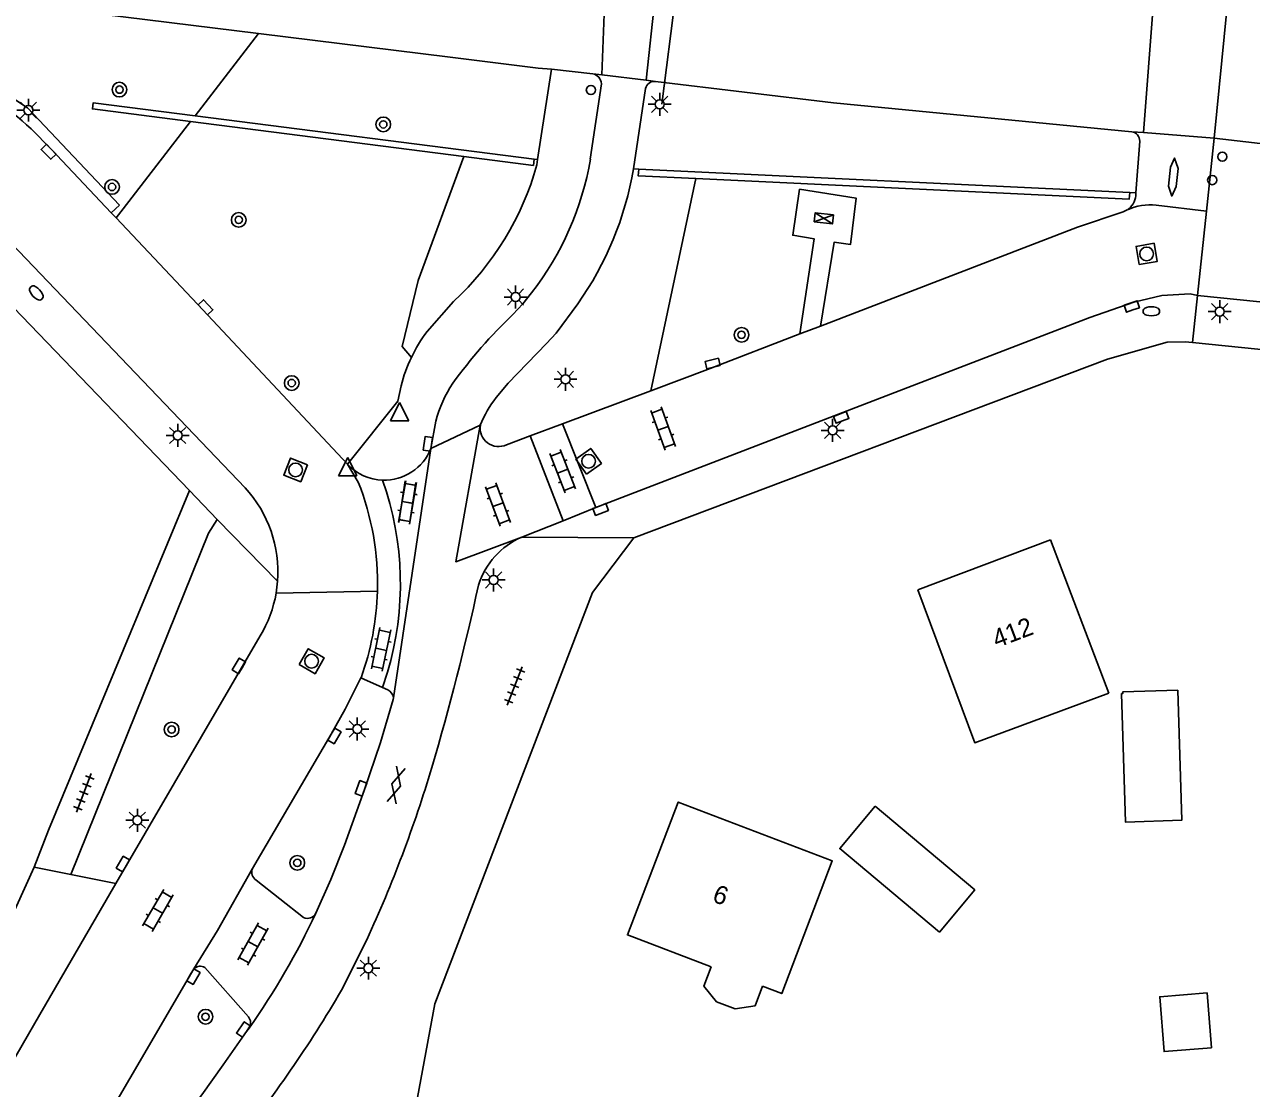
# Model space of a CAD drawing. Extents: x 132994 to 136000, y 393499 to 395512.
# Drawn here: x 133850.3 to 133917.2, y 394939.5 to 394997.5 of the extents above; entities that cross this region are included whole.
import ezdxf

# ---------------------------------------------------------------- set-up
doc = ezdxf.new("R2010")
doc.units = 0
for name, color, linetype in [('gg-anno-huisnummerreeks BGT', 7, 'Continuous'), ('gg-bbg-bijgebouw', 7, 'Continuous'), ('gg-bbg-gedigitaliseerde bebouwing', 7, 'Continuous'), ('gg-bbg-gedigitaliseerde bijgebouw', 7, 'Continuous'), ('gg-bbg-hoofdgebouw', 7, 'Continuous'), ('gg-knt-verharding', 7, 'Continuous'), ('gg-knt-verharding nz', 7, 'Continuous'), ('gt-grn-groengrens', 7, 'Continuous'), ('gt-grn-weggrens', 7, 'Continuous'), ('gt-knt-lijn portaal', 7, 'Continuous'), ('gt-symb-boom', 7, 'Continuous'), ('gt-symb-brandkraan', 7, 'Continuous'), ('gt-symb-drukknoppaal', 7, 'Continuous'), ('gt-symb-gesloten verharding', 7, 'Continuous'), ('gt-symb-klinker verharding', 7, 'Continuous'), ('gt-symb-kolk', 7, 'Continuous'), ('gt-symb-lichtmast', 7, 'Continuous'), ('gt-symb-rioolschacht', 7, 'Continuous'), ('gt-symb-tegel verharding', 7, 'Continuous'), ('gt-symb-verkeersregelinstallatiekast', 7, 'Continuous'), ('gt-symb-verkeersregelinstallatiepaal', 7, 'Continuous'), ('gt-symb-waterafsluiter', 7, 'Continuous')]:
    doc.layers.add(name, color=color, linetype=linetype)

# ---------------------------------------------------------------- blocks, each defined once
blk = doc.blocks.new('gt0-VIPAAL')
at = {"layer": 'gt-symb-verkeersregelinstallatiepaal'}
blk.add_circle((0, 0), 0.25, dxfattribs=at)
blk = doc.blocks.new('gt0-DPAAL')
at = {"layer": 'gt-symb-drukknoppaal'}
blk.add_circle((0, 0), 0.25, dxfattribs=at)
blk = doc.blocks.new('gt0-KOLK')
at = {"layer": 'gt-symb-kolk'}
blk.add_lwpolyline([(0, 0), (0.375, 0), (0.375, 0.4), (-0.375, 0.4), (-0.375, 0), (0, 0)], dxfattribs=at)
blk = doc.blocks.new('gt0-RS')
at = {"layer": 'gt-symb-rioolschacht'}
blk.add_lwpolyline([(-0.5, -0.5), (0.5, -0.5), (0.5, 0.5), (-0.5, 0.5)], close=True, dxfattribs=at)
blk.add_circle((0, 0), 0.375, dxfattribs=at)
blk = doc.blocks.new('gt0-BR')
at = {"layer": 'gt-symb-brandkraan'}
for centre, radius, start, end in [((-0.244, 0), 0.206, 107.56694, 252.43307), ((0.599, -2.664), 3, 106.89205, 107.56694), ((0, -0.691), 0.938, 73.10799, 106.89205), ((-0.599, -2.664), 3, 72.43309, 73.10799), ((0.244, 0), 0.206, 287.56695, 72.43309), ((0.599, 2.664), 3, 252.43307, 253.10797), ((0, 0.691), 0.938, 253.10797, 286.89206), ((-0.599, 2.664), 3, 286.89206, 287.56695)]:
    blk.add_arc(centre, radius, start, end, dxfattribs=at)
blk = doc.blocks.new('gt0-BOOM')
at = {"layer": 'gt-symb-boom'}
for radius in [0.4, 0.2]:
    blk.add_circle((0, 0), radius, dxfattribs=at)
blk = doc.blocks.new('gt0-LMAST')
at = {"layer": 'gt-symb-lichtmast'}
for p, q in [((-0.182, 0.173), (-0.447, 0.438)), ((-0.005, 0.246), (-0.005, 0.621)), ((0.172, 0.173), (0.437, 0.438)), ((-0.255, -0.004), (-0.63, -0.004)), ((-0.182, -0.181), (-0.447, -0.446)), ((-0.005, -0.254), (-0.005, -0.629)), ((0.437, -0.446), (0.172, -0.181)), ((0.245, -0.004), (0.62, -0.004))]:
    blk.add_line(p, q, dxfattribs=at)
blk.add_circle((-0.005, -0.004), 0.25, dxfattribs=at)
blk = doc.blocks.new('gt0-VRIKST')
at = {"layer": 'gt-symb-verkeersregelinstallatiekast'}
for p, q in [((-0.501, -0.249), (0.501, 0.249)), ((-0.501, 0.249), (0.501, -0.249))]:
    blk.add_line(p, q, dxfattribs=at)
blk.add_lwpolyline([(0.501, 0.249), (-0.501, 0.249), (-0.501, -0.249), (0.501, -0.249)], close=True, dxfattribs=at)
blk = doc.blocks.new('gt0-KL1')
at = {"layer": 'gt-symb-klinker verharding'}
for p, q in [((-1.15, 0.3), (1.15, 0.3)), ((-1, -0.3), (-1, 0.3)), ((-0.5, 0.3), (-0.5, 0.45)), ((0, -0.3), (0, 0.3)), ((0.5, 0.3), (0.5, 0.45)), ((1, -0.3), (1, 0.3)), ((-1.15, -0.3), (1.15, -0.3)), ((-0.5, -0.45), (-0.5, -0.3)), ((0.5, -0.45), (0.5, -0.3))]:
    blk.add_line(p, q, dxfattribs=at)
blk = doc.blocks.new('gt0-WAFSL')
at = {"layer": 'gt-symb-waterafsluiter'}
for p, q in [((-0.5, -0.333), (0, 0.667)), ((0, 0.667), (0.5, -0.333)), ((0.5, -0.333), (-0.5, -0.333))]:
    blk.add_line(p, q, dxfattribs=at)
blk = doc.blocks.new('gt0-TEG1')
at = {"layer": 'gt-symb-tegel verharding'}
for p, q in [((-1.125, 0), (1.125, 0)), ((-0.9, -0.25), (-0.9, 0.25)), ((-0.45, -0.25), (-0.45, 0.25)), ((0, -0.25), (0, 0.25)), ((0.45, -0.25), (0.45, 0.25)), ((0.9, -0.25), (0.9, 0.25))]:
    blk.add_line(p, q, dxfattribs=at)
blk = doc.blocks.new('gt0-GESVH1')
at = {"layer": 'gt-symb-gesloten verharding'}
for p, q in [((-0.992, -0.261), (0.008, 0.239)), ((0.008, -0.261), (-0.992, 0.239)), ((0.008, 0.239), (1.008, -0.261)), ((1.008, 0.239), (0.008, -0.261))]:
    blk.add_line(p, q, dxfattribs=at)

msp = doc.modelspace()

# ---------------------------------------------------------------- linework, layer by layer
at = {"layer": 'gg-bbg-bijgebouw'}
for points in [[(133910.122, 394960.997), (133910.197, 394961), (133910.194, 394961.08), (133913.191, 394961.174), (133913.414, 394954.078), (133910.336, 394953.981), (133910.122, 394960.997)], [(133896.675, 394954.842), (133894.743, 394952.535), (133900.186, 394947.976), (133902.118, 394950.283), (133896.675, 394954.842)]]:
    msp.add_lwpolyline(points, dxfattribs=at)
at = {"layer": 'gg-bbg-gedigitaliseerde bebouwing'}
for points in [[(133899, 394966.65), (133902.114, 394958.31), (133909.431, 394961.02)], [(133888.022, 394944.169), (133889.034, 394943.785), (133890.127, 394943.962), (133890.531, 394945.029)]]:
    msp.add_lwpolyline(points, dxfattribs=at)
at = {"layer": 'gg-bbg-gedigitaliseerde bijgebouw'}
msp.add_lwpolyline([(133915.04, 394941.667), (133914.799, 394944.658), (133912.208, 394944.449), (133912.448, 394941.459), (133915.04, 394941.667)], dxfattribs=at)
at = {"layer": 'gg-bbg-hoofdgebouw'}
for p, q in [((133899, 394966.65), (133906.24, 394969.38)), ((133906.24, 394969.38), (133909.431, 394961.02))]:
    msp.add_line(p, q, dxfattribs=at)
for points in [[(133890.531, 394945.029), (133891.58, 394944.63), (133894.34, 394951.87), (133885.93, 394955.07), (133883.16, 394947.83), (133887.727, 394946.094)], [(133887.727, 394946.094), (133887.322, 394945.027), (133888.022, 394944.169)]]:
    msp.add_lwpolyline(points, dxfattribs=at)
at = {"layer": 'gg-knt-verharding'}
for p, q in [((133873.479, 394995.704), (133863.026, 394996.992)), ((133879.016, 394995.05), (133878.256, 394990.126)), ((133881.265, 394994.795), (133879.016, 394995.05)), ((133881.132, 394990.14), (133881.733, 394994.255)), ((133884.151, 394993.998), (133883.483, 394989.615)), ((133910.686, 394991.635), (133911.333, 394991.593)), ((133911.333, 394991.593), (133915.182, 394991.281)), ((133910.912, 394988.302), (133911.118, 394991.117)), ((133915.182, 394991.281), (133914.759, 394987.306)), ((133918.173, 394990.943), (133915.182, 394991.281)), ((133878.256, 394990.126), (133878.21, 394989.826)), ((133862.288, 394972.217), (133846.386, 394988.819)), ((133859.247, 394972.063), (133843.346, 394988.59)), ((133910.901, 394988.15), (133910.912, 394988.302)), ((133912.018, 394987.641), (133914.759, 394987.306)), ((133854.985, 394987.216), (133855.244, 394986.942)), ((133910.442, 394987.376), (133910.223, 394987.265)), ((133914.759, 394987.306), (133914.27, 394982.706)), ((133873.672, 394982.381), (133872.22, 394980.739)), ((133908.4, 394981.51), (133881.431, 394971.142)), ((133892.571, 394980.611), (133893.687, 394981.04)), ((133887.68, 394978.73), (133892.571, 394980.611)), ((133884.428, 394977.512), (133887.68, 394978.73)), ((133870.807, 394977.776), (133870.626, 394976.95)), ((133879.614, 394975.708), (133884.428, 394977.512)), ((133867.886, 394973.502), (133870.626, 394976.95)), ((133872.427, 394974.363), (133872.702, 394975.851)), ((133877.85, 394975.048), (133879.614, 394975.708)), ((133881.431, 394971.142), (133879.614, 394975.708)), ((133876.553, 394974.562), (133877.85, 394975.048)), ((133877.85, 394975.048), (133879.652, 394970.417)), ((133870.381, 394960.765), (133872.427, 394974.363)), ((133868.464, 394972.526), (133867.886, 394973.502)), ((133851.551, 394953.543), (133859.247, 394972.063)), ((133879.652, 394970.417), (133881.431, 394971.142)), ((133860.761, 394970.479), (133860.284, 394969.736)), ((133864.063, 394967.123), (133860.761, 394970.479)), ((133879.652, 394970.417), (133877.387, 394969.525)), ((133852.769, 394951.12), (133860.284, 394969.736)), ((133863.982, 394966.47), (133864.063, 394967.123)), ((133855.239, 394950.627), (133863.113, 394964.14)), ((133870.057, 394962.157), (133869.782, 394961.321)), ((133868.615, 394961.851), (133867.754, 394960.139)), ((133869.782, 394961.321), (133868.615, 394961.851)), ((133870.073, 394961.189), (133869.782, 394961.321)), ((133850.771, 394951.519), (133851.551, 394953.543)), ((133855.239, 394950.627), (133851.089, 394943.477)), ((133852.769, 394951.12), (133855.239, 394950.627)), ((133862.898, 394950.816), (133865.481, 394948.778)), ((133868.937, 394947.565), (133867.551, 394944.812)), ((133862.467, 394943.354), (133860.091, 394946.056)), ((133851.089, 394943.477), (133849.149, 394940.135))]:
    msp.add_line(p, q, dxfattribs=at)
for points in [[(133863.026, 394996.992), (133848.377, 394998.796), (133838.166, 395000)], [(133873.479, 394995.704), (133878.293, 394995.107), (133879.016, 394995.05)], [(133910.686, 394991.635), (133894.413, 394993.207), (133884.689, 394994.385)], [(133850.609, 394991.794), (133851.705, 394990.685), (133854.985, 394987.216)], [(133912.695, 394988.663), (133912.868, 394988.127), (133913.108, 394988.649), (133913.219, 394989.631), (133913.023, 394990.197), (133912.789, 394989.699), (133912.695, 394988.663)], [(133893.687, 394981.04), (133894.436, 394985.612), (133895.328, 394985.481), (133895.641, 394988.018), (133892.55, 394988.5), (133892.181, 394985.991), (133893.343, 394985.804), (133892.571, 394980.611)], [(133855.244, 394986.942), (133859.986, 394981.927), (133867.886, 394973.502)], [(133893.687, 394981.04), (133907.73, 394986.44), (133910.223, 394987.265)], [(133876.904, 394981.678), (133877.446, 394982.244), (133877.927, 394982.857)], [(133914.27, 394982.706), (133913.87, 394982.8), (133912.33, 394982.7), (133910.79, 394982.35), (133908.4, 394981.51)], [(133880.446, 394982.245), (133879.266, 394980.647), (133878.748, 394980.093), (133876.644, 394977.926), (133875.995, 394977.142)], [(133913.996, 394980.139), (133913.59, 394980.18), (133912.61, 394980.16), (133909.36, 394979.23), (133883.51, 394969.49)], [(133942.56, 394977.82), (133942.56, 394977.66), (133938.56, 394978.04), (133938.51, 394977.92), (133924.9, 394979.28), (133924.87, 394979.04), (133913.996, 394980.139)], [(133875.128, 394975.629), (133873.786, 394968.181), (133877.387, 394969.525)], [(133871.116, 394935.811), (133872.649, 394944.058), (133881.252, 394966.506), (133883.51, 394969.49)], [(133866.152, 394949.008), (133866.965, 394950.851), (133867.713, 394952.715), (133868.808, 394955.756), (133869.674, 394958.314), (133870.376, 394960.662), (133870.381, 394960.765)], [(133867.754, 394960.139), (133866.994, 394958.779), (133862.697, 394951.443)], [(133850.771, 394951.519), (133849.288, 394948.238), (133845.885, 394942.434)], [(133859.495, 394945.981), (133860.778, 394948.072), (133862.697, 394951.443)], [(133851.898, 394932.933), (133852.499, 394934.006), (133859.495, 394945.981)], [(133854.954, 394932.825), (133856.802, 394935.184), (133858.69, 394937.504), (133859.926, 394939.095), (133861.097, 394940.731), (133862.358, 394942.553), (133862.505, 394942.738)]]:
    msp.add_lwpolyline(points, dxfattribs=at)
for centre, radius, start, end in [((133842.053, 394982.69), 12.494, 46.77674, 70.9578), ((133881.168, 394994.238), 0.566, 1.74583, 80.08294), ((133884.637, 394993.89), 0.498, 84.03151, 167.42575), ((133910.624, 394991.145), 0.494, 356.81029, 82.84436), ((133865.151, 394992.826), 16.206, 322.03586, 350.45882), ((133862.802, 394994.112), 15.993, 312.8173, 344.45503), ((133865.828, 394992.579), 17.902, 324.74061, 350.46863), ((133909.866, 394988.241), 1.039, 303.67342, 354.98873), ((133911.72, 394984.596), 3.059, 84.4031, 114.68658), ((133896.917, 394960.915), 28.838, 133.94682, 143.87147), ((133878.83, 394975.774), 8.267, 143.0909, 154.54072), ((133878.815, 394975.768), 8.256, 154.45813, 165.92581), ((133879.298, 394974.145), 6.813, 146.37387, 165.5007), ((133880.847, 394973.357), 6.154, 142.04055, 158.33113), ((133876.126, 394975.476), 1.009, 171.3007, 295.04962), ((133869.885, 394975.359), 2.73, 268.15784, 338.60676), ((133869.888, 394975.359), 2.73, 222.84913, 268.09591), ((133857.316, 394967.628), 6.766, 355.71613, 42.70556), ((133854.423, 394966.988), 15.094, 358.44616, 21.52362), ((133853.924, 394966.996), 16.843, 343.30334, 19.54089), ((133879.093, 394965.608), 4.272, 113.5374, 162.25859), ((133738.544, 394996.467), 139.644, 343.56768, 347.78044), ((133857.319, 394967.628), 6.763, 328.95167, 350.14119), ((133854.419, 394966.99), 15.098, 340.09905, 358.43929), ((133869.891, 394960.733), 0.491, 3.72684, 68.2636), ((133803.273, 394977.714), 72.254, 335.33813, 343.3108), ((133863.13, 394951.236), 0.48, 154.49329, 241.05573), ((133827.299, 394967.412), 42.992, 324.97601, 334.6544), ((133865.701, 394949.229), 0.502, 243.92413, 333.91643), ((133859.846, 394945.596), 0.521, 61.97854, 132.36614), ((133809.023, 394978.984), 67.774, 320.95606, 329.7215), ((133862.066, 394943.02), 0.522, 327.26355, 39.79647)]:
    msp.add_arc(centre, radius, start, end, dxfattribs=at)
at = {"layer": 'gg-knt-verharding nz'}
for p, q in [((133882.166, 395005.026), (133881.759, 394994.736)), ((133885.276, 395004.635), (133884.171, 394994.447)), ((133911.863, 394998.7), (133911.333, 394991.593)), ((133915.881, 394998.286), (133915.182, 394991.281)), ((133881.265, 394994.795), (133881.759, 394994.736)), ((133881.759, 394994.736), (133884.171, 394994.447)), ((133884.171, 394994.447), (133884.689, 394994.385)), ((133914.27, 394982.706), (133934.487, 394980.66)), ((133850.771, 394951.519), (133852.769, 394951.12))]:
    msp.add_line(p, q, dxfattribs=at)
at = {"layer": 'gt-grn-groengrens'}
for p, q in [((133863.026, 394996.992), (133859.56, 394992.514)), ((133859.313, 394992.195), (133855.629, 394987.436)), ((133859.313, 394992.195), (133874.233, 394990.289)), ((133878.073, 394990.149), (133859.56, 394992.514)), ((133874.233, 394990.289), (133878.028, 394989.804)), ((133878.028, 394989.804), (133878.073, 394990.149)), ((133878.073, 394990.149), (133878.256, 394990.126)), ((133883.774, 394989.605), (133883.483, 394989.615)), ((133910.58, 394988.318), (133883.774, 394989.605)), ((133886.889, 394989.088), (133884.428, 394977.512)), ((133910.58, 394988.318), (133910.912, 394988.302)), ((133854.985, 394987.216), (133855.435, 394987.641)), ((133855.244, 394986.942), (133855.629, 394987.436))]:
    msp.add_line(p, q, dxfattribs=at)
for points in [[(133846.453, 394995.188), (133848.227, 394994.385), (133850.419, 394992.944), (133855.435, 394987.641)], [(133859.56, 394992.514), (133854.003, 394993.224), (133853.958, 394992.879), (133859.313, 394992.195)], [(133874.233, 394990.289), (133871.738, 394983.522), (133870.862, 394979.922), (133871.366, 394979.328)], [(133883.774, 394989.605), (133883.736, 394989.239), (133886.889, 394989.088)], [(133886.889, 394989.088), (133910.542, 394987.952), (133910.58, 394988.318)]]:
    msp.add_lwpolyline(points, dxfattribs=at)
at = {"layer": 'gt-grn-weggrens'}
for p, q in [((133914.27, 394982.706), (133913.996, 394980.139)), ((133872.427, 394974.363), (133875.128, 394975.629)), ((133860.761, 394970.479), (133859.247, 394972.063)), ((133883.51, 394969.49), (133877.387, 394969.525)), ((133869.511, 394966.579), (133863.982, 394966.47))]:
    msp.add_line(p, q, dxfattribs=at)
at = {"layer": 'gt-knt-lijn portaal'}
msp.add_line((133885.041, 394993.151), (133886.188, 395002.329), dxfattribs=at)

# ---------------------------------------------------------------- block references
at = {"layer": 'gt-symb-boom'}
for p in [(133855.432, 394993.934), (133869.832, 394992.04), (133855.027, 394988.625), (133861.942, 394986.831), (133889.386, 394980.56), (133864.832, 394977.932), (133858.28, 394959.031), (133865.138, 394951.758), (133860.131, 394943.363)]:
    msp.add_blockref('gt0-BOOM', p, dxfattribs=at)
at = {"layer": 'gt-symb-brandkraan', "rotation": -47.79566231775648}
msp.add_blockref('gt0-BR', (133850.893, 394982.843), dxfattribs=at)
at = {"layer": 'gt-symb-brandkraan'}
msp.add_blockref('gt0-BR', (133911.753, 394981.844), dxfattribs=at)
at = {"layer": 'gt-symb-drukknoppaal'}
msp.add_blockref('gt0-DPAAL', (133915.076, 394989.001), dxfattribs=at)
at = {"layer": 'gt-symb-gesloten verharding', "rotation": 75.5744682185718}
msp.add_blockref('gt0-GESVH1', (133870.525, 394956.001), dxfattribs=at)
at = {"layer": 'gt-symb-klinker verharding'}
for p, rotation in [((133885.102, 394975.454), 109.99289397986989), ((133879.624, 394973.117), -68.71983369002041), ((133871.161, 394971.416), 80.15137761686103), ((133871.145, 394971.416), -98.62422873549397), ((133876.091, 394971.299), 109.99289397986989), ((133869.711, 394963.404), 78.34159837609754), ((133857.527, 394949.16), 59.871399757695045), ((133862.721, 394947.327), 60.87308789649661)]:
    msp.add_blockref('gt0-KL1', p, dxfattribs=dict(at, rotation=rotation))
at = {"layer": 'gt-symb-kolk'}
for p, rotation in [((133851.705, 394990.685), 134.67584063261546), ((133859.986, 394981.927), -46.62038198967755), ((133910.75, 394981.918), 19.033079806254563), ((133887.851, 394978.801), 13.883418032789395), ((133894.897, 394975.869), 21.099212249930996), ((133872.461, 394974.586), 81.37577126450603), ((133881.626, 394971.221), -158.82666847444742), ((133862.124, 394962.397), 59.07554097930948), ((133866.994, 394958.779), -120.38423729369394), ((133868.808, 394955.756), 70.18818811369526), ((133855.795, 394951.595), 59.409564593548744), ((133859.295, 394945.651), -120.71819066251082), ((133862.358, 394942.553), 55.3084711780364)]:
    msp.add_blockref('gt0-KOLK', p, dxfattribs=dict(at, rotation=rotation))
at = {"layer": 'gt-symb-lichtmast'}
for p in [(133884.922, 394993.138), (133850.469, 394992.821), (133877.056, 394982.625), (133915.487, 394981.831), (133879.78, 394978.141), (133858.615, 394975.076), (133894.362, 394975.35), (133875.856, 394967.193), (133868.42, 394959.058), (133856.413, 394954.086), (133869.025, 394946.015)]:
    msp.add_blockref('gt0-LMAST', p, dxfattribs=at)
at = {"layer": 'gt-symb-rioolschacht'}
for p, rotation in [((133911.497, 394984.976), 9.725965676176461), ((133881.04, 394973.665), 35.31121343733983), ((133865.045, 394973.19), 158.59226005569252), ((133865.921, 394962.757), -29.87282104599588)]:
    msp.add_blockref('gt0-RS', p, dxfattribs=dict(at, rotation=rotation))
at = {"layer": 'gt-symb-tegel verharding'}
for p, rotation in [((133877.003, 394961.409), -111.22676826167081), ((133853.487, 394955.578), 68.95425918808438)]:
    msp.add_blockref('gt0-TEG1', p, dxfattribs=dict(at, rotation=rotation))
at = {"layer": 'gt-symb-verkeersregelinstallatiekast', "rotation": -6.770657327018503}
msp.add_blockref('gt0-VRIKST', (133893.877, 394986.913), dxfattribs=at)
at = {"layer": 'gt-symb-verkeersregelinstallatiepaal'}
for p in [(133881.163, 394993.916), (133915.63, 394990.278)]:
    msp.add_blockref('gt0-VIPAAL', p, dxfattribs=at)
at = {"layer": 'gt-symb-waterafsluiter'}
for p in [(133870.724, 394976.201), (133867.895, 394973.209)]:
    msp.add_blockref('gt0-WAFSL', p, dxfattribs=at)

# ---------------------------------------------------------------- texts
at = {"layer": 'gg-anno-huisnummerreeks BGT'}
for s, rotation, p in [('412', 20.7, (133903.311, 394963.465)), ('6', 339.1, (133887.731, 394949.672))]:
    msp.add_text(s, height=1, rotation=rotation, dxfattribs=at).set_placement(p)

doc.saveas('drawing.dxf')
